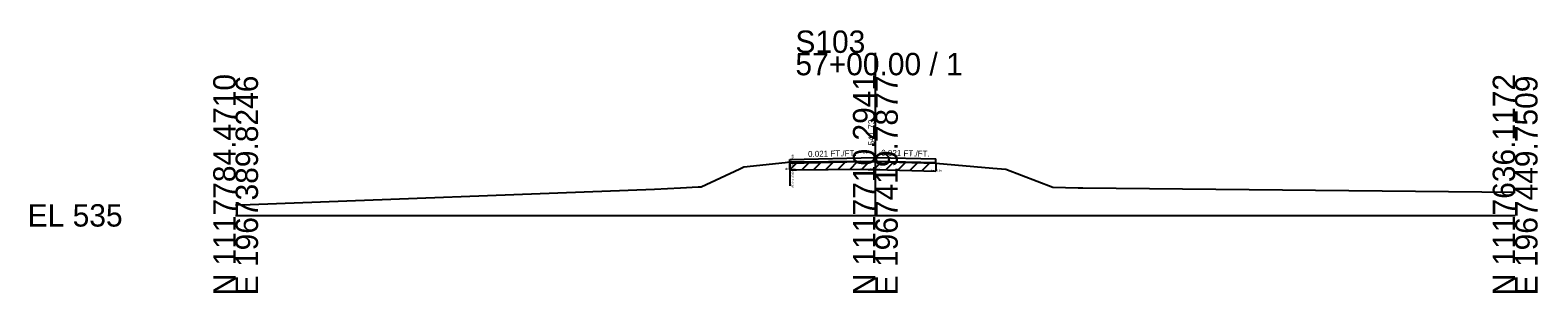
# Model space of a CAD drawing. Extents: x -26 to 163, y -10 to 24018.
# Drawn here: x -25.7 to 162.8, y 6490.3 to 6523.2 of the extents above; entities that cross this region are included whole.
import ezdxf

# ---------------------------------------------------------------- set-up
doc = ezdxf.new("R2010")
doc.units = 0
for name, color, linetype in [('RD_GPK_XS_Cell', 7, 'Continuous'), ('RD_XS_ExGround', 7, 'Continuous'), ('RD_XS_ExPaveRet', 7, 'Continuous'), ('RD_XS_Misc_Line', 7, 'Continuous'), ('RD_XS_PaveOvlay_CP', 7, 'Continuous'), ('RD_XS_TX_Elev_EX', 7, 'Continuous'), ('RD_XS_TX_ExEOP', 7, 'Continuous'), ('RD_XS_TX_Notes', 7, 'Continuous'), ('RD_XS_TX_Profile', 7, 'Continuous'), ('RD_XS_TX_Slope', 7, 'Continuous')]:
    doc.layers.add(name, color=color, linetype=linetype)

msp = doc.modelspace()

# ---------------------------------------------------------------- linework, layer by layer
at = {"layer": 'RD_GPK_XS_Cell'}
for p, q in [((80, 6500), (80, 6520.33)), ((0, 6500), (80, 6500)), ((80, 6500), (160, 6500))]:
    msp.add_line(p, q, dxfattribs=at)
at = {"layer": 'RD_XS_ExGround'}
msp.add_lwpolyline([(0, 6501.33), (1.81, 6501.37), (52.37, 6503.3), (55.64, 6503.44), (57.86, 6503.56), (58.21, 6503.57), (63.03, 6505.83), (63.57, 6506.07), (68.72, 6506.62), (69.3, 6506.69), (70.15, 6506.69), (78.11, 6506.78), (79.11, 6506.75), (80, 6506.73), (87.54, 6506.52), (94.69, 6505.92), (96.33, 6505.78), (102.19, 6503.51), (105.35, 6503.43), (105.94, 6503.45), (160, 6502.91)], dxfattribs=at)
at = {"layer": 'RD_XS_ExPaveRet'}
for p, q in [((69.3, 6505.69), (70.31, 6506.7)), ((69.3, 6505.69), (69.3, 6506.69)), ((70.8, 6505.7), (71.81, 6506.71)), ((72.3, 6505.72), (73.31, 6506.73)), ((73.8, 6505.73), (74.81, 6506.74)), ((75.3, 6505.75), (76.31, 6506.76)), ((76.8, 6505.76), (77.81, 6506.77)), ((78.3, 6505.77), (79.28, 6506.75)), ((79.8, 6505.73), (80.78, 6506.71)), ((81.3, 6505.69), (82.28, 6506.67)), ((82.8, 6505.65), (83.78, 6506.62)), ((84.3, 6505.61), (85.28, 6506.58)), ((85.8, 6505.57), (86.78, 6506.54)), ((87.54, 6506.52), (87.54, 6505.52)), ((69.3, 6505.69), (70.15, 6505.69)), ((70.15, 6505.69), (78.11, 6505.78)), ((78.11, 6505.78), (79.11, 6505.75)), ((79.11, 6505.75), (80, 6505.73)), ((80, 6505.73), (87.54, 6505.52))]:
    msp.add_line(p, q, dxfattribs=at)
at = {"layer": 'RD_XS_Misc_Line'}
msp.add_line((69.3, 6506.69), (69.3, 6503.69), dxfattribs=at)
at = {"layer": 'RD_XS_PaveOvlay_CP'}
for p, q in [((69.3, 6507.01), (80, 6507.23)), ((69.3, 6506.69), (69.3, 6507.01)), ((80, 6506.73), (69.3, 6506.51)), ((80, 6507.23), (87.54, 6507.07)), ((87.54, 6506.57), (80, 6506.73)), ((87.54, 6506.52), (87.54, 6507.07))]:
    msp.add_line(p, q, dxfattribs=at)

# ---------------------------------------------------------------- texts
at = {"layer": 'RD_GPK_XS_Cell'}
for s, p in [('S103', (70, 6520.33)), ('57+00.00 / 1', (70, 6517.53)), ('EL 535', (-26, 6498.6))]:
    msp.add_text(s, height=2.8, dxfattribs=at).set_placement(p)
for s, p in [('N 1117784.4710', (0, 6490)), ('E 1967389.8246', (2.8, 6490)), ('N 1117710.2941', (80, 6490)), ('E 1967419.7877', (82.8, 6490)), ('N 1117636.1172', (160, 6490)), ('E 1967449.7509', (162.8, 6490))]:
    msp.add_text(s, height=2.8, rotation=90, dxfattribs=at).set_placement(p)
at = {"layer": 'RD_XS_TX_Elev_EX'}
msp.add_text('541.73', height=0.8, rotation=90, dxfattribs=at).set_placement((79.9, 6508.73))
at = {"layer": 'RD_XS_TX_ExEOP'}
for s, p in [('EOP-L', (69.25, 6507.01)), ('EOP-R', (87.49, 6507.07))]:
    msp.add_text(s, height=0.1, rotation=270, dxfattribs=at).set_placement(p)
at = {"layer": 'RD_XS_TX_Notes'}
msp.add_text(' Min. Distance @CP = -0.18', height=0.25, rotation=270, dxfattribs=at).set_placement((69.55, 6507.78))
for s, p in [('Elev. @CL = 542.23', (78.48, 6507.73)), (' dE= 0.32', (68.59, 6505.69)), (' dE= 0.50', (79.29, 6505.73)), (' dE= 0.55', (86.83, 6505.52))]:
    msp.add_text(s, height=0.25, dxfattribs=at).set_placement(p)
at = {"layer": 'RD_XS_TX_Profile'}
msp.add_text('CL', height=0.25, dxfattribs=at).set_placement((79.77, 6507.23))
at = {"layer": 'RD_XS_TX_Slope'}
for rotation, p in [(1.1916, (71.59, 6507.3)), (358.8084, (80.72, 6507.46))]:
    msp.add_text('0.021 FT./FT.', height=0.75, rotation=rotation, dxfattribs=at).set_placement(p)

doc.saveas('drawing.dxf')
